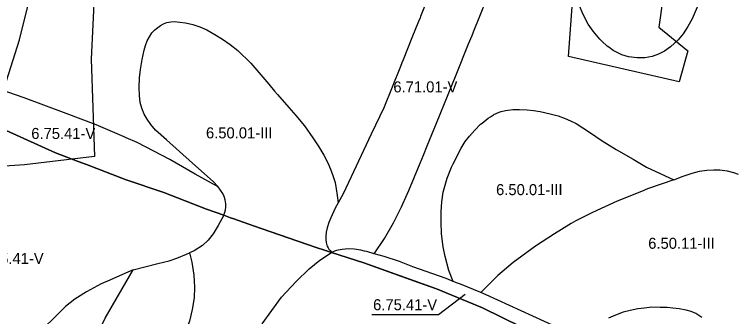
# Model space of a CAD drawing. Extents: x -555156 to -540209, y -1046851 to -1035695.
# Drawn here: x -543276 to -542621, y -1040830 to -1040556 of the extents above; entities that cross this region are included whole.
import ezdxf

# ---------------------------------------------------------------- set-up
doc = ezdxf.new("R2010")
doc.units = 0
for name, color, linetype in [('Vrstva 27', 7, 'Continuous'), ('Vrstva 28', 7, 'Continuous'), ('Vrstva 29', 7, 'Continuous')]:
    doc.layers.add(name, color=color, linetype=linetype)

msp = doc.modelspace()

# ---------------------------------------------------------------- linework, layer by layer
at = {"layer": 'Vrstva 27'}
msp.add_lwpolyline([(-542951.97, -1040828.05), (-542891.45, -1040828.05), (-542867.16, -1040809.73)], dxfattribs=at)
at = {"layer": 'Vrstva 28'}
for points in [[(-542875, -1040398.79), (-542873.7, -1040418.14), (-542873.31, -1040426.89), (-542872.91, -1040435.93), (-542872.91, -1040450.05), (-542873.7, -1040461.3), (-542875.53, -1040471.76), (-542876, -1040473.5), (-542878.66, -1040483.27), (-542881.47, -1040491.53), (-542883.11, -1040496.34), (-542907.05, -1040556.47), (-542907.61, -1040557.89), (-542908.19, -1040559.33), (-542909.52, -1040562.62), (-542915.49, -1040577.42), (-542923.48, -1040597.25), (-542924.63, -1040600.11), (-542925.9, -1040603.26), (-542941.01, -1040640.73), (-542952.35, -1040664.73), (-542973.03, -1040708.47), (-542977.75, -1040718.65), (-542982.34, -1040726.85)], [(-542719.25, -1040594.65), (-542725.26, -1040592.75), (-542733.18, -1040588.71), (-542737.18, -1040585.9), (-542738.71, -1040584.83), (-542743.47, -1040580.28), (-542745.28, -1040578.55), (-542749.82, -1040573.23), (-542751.4, -1040571.38), (-542756.03, -1040564.95), (-542760.37, -1040556.13), (-542763.8, -1040548.21), (-542766.94, -1040539.55), (-542769.03, -1040531.03), (-542770.82, -1040520.56), (-542775.87, -1040486.78), (-542776.18, -1040484.69)], [(-542647.85, -1040518.92), (-542650.77, -1040529.44), (-542650.84, -1040529.68), (-542653.68, -1040539.69), (-542657.11, -1040549.67), (-542661.75, -1040559.98), (-542665.63, -1040567.16), (-542669.96, -1040573.73), (-542674.29, -1040579.26), (-542681.46, -1040585.54), (-542686.69, -1040589.27), (-542692.07, -1040592.11), (-542698.04, -1040594.21), (-542704.46, -1040595.4), (-542711.63, -1040595.55), (-542719.25, -1040594.65)], [(-542940.22, -1040759.1), (-542932.3, -1040745.05), (-542924.98, -1040730.4), (-542919.71, -1040718.95), (-542918.37, -1040715.72), (-542908.09, -1040690.87), (-542905.17, -1040683.71), (-542901.7, -1040675.21), (-542893.31, -1040654.67), (-542882.73, -1040628.76), (-542881.46, -1040625.65), (-542875.38, -1040610.78), (-542864.2, -1040582.89), (-542861.09, -1040575.12), (-542859.74, -1040571.76), (-542841.99, -1040527.48)], [(-543091.12, -1040712.41), (-543095.47, -1040707.46), (-543114.31, -1040690.82), (-543137.83, -1040669.9), (-543147.84, -1040660.93), (-543152.02, -1040656), (-543155.46, -1040650.92), (-543158.14, -1040646.58), (-543160.24, -1040641.2), (-543161.58, -1040635.82), (-543162.33, -1040629.7), (-543162.63, -1040622.37), (-543162.36, -1040613.52), (-543161.47, -1040606.05), (-543159.97, -1040596.93), (-543158.18, -1040588.41), (-543156.94, -1040584.27), (-543155.32, -1040580), (-543153.27, -1040576.33), (-543150.97, -1040572.82), (-543148.24, -1040570.01), (-543146.8, -1040568.77), (-543145.76, -1040567.87), (-543143.29, -1040566.08), (-543140.56, -1040564.63), (-543137.57, -1040563.43), (-543133.98, -1040562.75), (-543130.57, -1040562.58), (-543125.62, -1040563), (-543120.58, -1040563.6), (-543113.84, -1040565.22), (-543107.52, -1040567.44), (-543101.38, -1040570.18), (-543094.12, -1040574.28), (-543087.04, -1040578.55), (-543080.21, -1040583.24), (-543073.13, -1040588.88), (-543061.35, -1040600.15), (-543045.22, -1040619.45), (-543039.87, -1040625.62), (-543037.16, -1040628.75), (-543027.02, -1040640.47), (-543020.59, -1040647.79), (-543012.97, -1040657.06), (-543005.36, -1040667.97), (-542999.83, -1040676.04), (-542995.2, -1040683.81), (-542991.76, -1040690.53), (-542989.25, -1040696.3), (-542987.11, -1040702.19), (-542985.15, -1040708.51), (-542984.04, -1040714.23), (-542983.1, -1040720.38), (-542982.34, -1040726.85)], [(-543091.12, -1040712.41), (-543111.91, -1040700.84), (-543134.91, -1040687.76), (-543164.45, -1040672.33), (-543174.27, -1040667.88), (-543176.28, -1040666.97), (-543193.18, -1040659.82), (-543201.63, -1040656.25), (-543228.82, -1040646.05), (-543266.64, -1040631.83), (-543288.6, -1040624.24), (-543307.42, -1040617.96), (-543322.58, -1040614.04), (-543328.36, -1040612.54), (-543337.74, -1040610.12), (-543337.84, -1040610.1), (-543342.85, -1040609.11), (-543353.68, -1040606.98), (-543361.64, -1040605.12), (-543376.95, -1040601.54), (-543406.05, -1040594.73)], [(-543085.78, -1040738.2), (-543101.67, -1040732.49), (-543140.14, -1040717.52), (-543174.28, -1040705.94), (-543210.23, -1040692.22), (-543217.71, -1040689.38), (-543238.43, -1040681.52), (-543299.21, -1040654.19), (-543333.45, -1040639.76), (-543338.53, -1040637.62), (-543366.74, -1040625.24), (-543373.17, -1040622.42), (-543394.76, -1040609.36), (-543404.86, -1040603.25), (-543412.12, -1040599.04)], [(-543404.86, -1040603.25), (-543394.76, -1040609.36), (-543373.17, -1040622.42), (-543366.74, -1040625.24), (-543338.53, -1040637.62), (-543333.45, -1040639.76), (-543299.21, -1040654.19), (-543238.43, -1040681.52), (-543217.71, -1040689.38), (-543210.23, -1040692.22), (-543174.28, -1040705.94), (-543140.14, -1040717.52), (-543101.67, -1040732.49), (-543085.78, -1040738.2)], [(-542878.08, -1040798.15), (-542882.13, -1040788.09), (-542885.52, -1040775.54), (-542887.35, -1040766.64), (-542888.66, -1040754.87), (-542888.92, -1040744.15), (-542888.92, -1040735), (-542888.4, -1040726.1), (-542887.09, -1040717.21), (-542883.69, -1040704.4), (-542879.54, -1040694.69), (-542878.21, -1040691.58), (-542870.87, -1040677.46), (-542867.2, -1040671.39), (-542863.44, -1040666.52), (-542858.49, -1040660.97), (-542853.28, -1040655.68), (-542851.98, -1040654.63), (-542846.54, -1040650.21), (-542844.41, -1040648.83), (-542841.67, -1040647.05), (-542841.4, -1040646.93), (-542836.47, -1040644.66), (-542834.66, -1040644.17), (-542830.75, -1040643.12), (-542824.09, -1040642.36), (-542817.95, -1040642.27), (-542811.29, -1040642.53), (-542805.4, -1040643.21), (-542799.34, -1040643.98), (-542790.46, -1040646.11), (-542783.12, -1040648.16), (-542776.64, -1040650.47), (-542771.77, -1040652.6), (-542766.87, -1040655.03), (-542754.77, -1040662.95), (-542743.12, -1040670.72), (-542730.57, -1040678.65), (-542715.19, -1040687.46), (-542703.09, -1040694.49), (-542678.39, -1040706.13)], [(-542678.39, -1040706.13), (-542669.87, -1040702.69), (-542661.81, -1040700.15), (-542654.93, -1040698.2), (-542648.34, -1040697.18), (-542642.19, -1040696.84), (-542636.56, -1040697.01), (-542630.07, -1040698.03), (-542624.18, -1040699.4), (-542619.91, -1040700.94)], [(-542678.39, -1040706.13), (-542701.16, -1040714.05), (-542703.66, -1040714.92), (-542706, -1040715.87), (-542729.54, -1040725.39), (-542752.02, -1040735.59), (-542767.09, -1040743.33), (-542771.36, -1040745.52), (-542786.52, -1040754.94), (-542803.51, -1040766.19), (-542823.9, -1040781.09), (-542837.75, -1040792.86)], [(-543085.01, -1040735.3), (-543084.46, -1040733.25), (-543084.12, -1040730.77), (-543084.12, -1040727.87), (-543084.54, -1040724.2), (-543085.57, -1040721.21), (-543086.85, -1040718.47), (-543088.81, -1040715.49), (-543091.12, -1040712.41)], [(-542982.34, -1040726.85), (-542985.01, -1040731.63), (-542988.94, -1040740.51), (-542990.81, -1040744.61), (-542992.26, -1040749.65), (-542993.29, -1040753.58), (-542993.51, -1040757.47), (-542993.51, -1040760.4), (-542993.26, -1040762.6), (-542992.78, -1040764.45), (-542992.57, -1040765.08), (-542992.19, -1040766.26), (-542991.41, -1040767.67), (-542991.32, -1040767.83), (-542990.73, -1040768.89), (-542989.7, -1040770.16)], [(-543085.78, -1040738.2), (-543090.89, -1040747.49), (-543095.61, -1040754.88), (-543099.97, -1040760.7), (-543105.3, -1040765.54), (-543112.69, -1040770.39), (-543117.02, -1040772.37)], [(-543085.78, -1040738.2), (-543085.01, -1040735.3)], [(-543085.78, -1040738.2), (-543079.73, -1040740.37), (-543076.8, -1040741.42), (-543059.07, -1040747.79), (-543036.45, -1040755.62), (-543002.41, -1040767.4), (-542994.61, -1040769.9), (-542988.31, -1040771.92)], [(-542988.31, -1040771.92), (-542994.61, -1040769.9), (-543002.41, -1040767.4), (-543059.07, -1040747.79), (-543076.8, -1040741.42), (-543079.73, -1040740.37), (-543085.78, -1040738.2)], [(-542949.59, -1040773.02), (-542940.22, -1040759.1)], [(-543168.15, -1040787.72), (-543145.63, -1040782.02), (-543135.33, -1040779.36), (-543128.43, -1040776.93), (-543119.59, -1040773.54), (-543117.02, -1040772.37)], [(-543117.02, -1040772.37), (-543114.91, -1040780.64)], [(-543051.23, -1040836.43), (-543033.64, -1040812.47), (-543020.29, -1040798.26), (-543008.63, -1040786.6), (-542998.88, -1040778.96), (-542988.31, -1040771.92)], [(-542989.7, -1040770.16), (-542988.31, -1040771.92)], [(-542949.59, -1040773.02), (-542956.25, -1040771.14), (-542958.47, -1040770.67), (-542961.88, -1040769.94), (-542967.77, -1040769), (-542973.4, -1040768.66), (-542978.7, -1040769.09), (-542982.28, -1040769.69), (-542983.7, -1040770.12), (-542985.75, -1040770.74), (-542988.31, -1040771.92)], [(-542988.31, -1040771.92), (-542959.22, -1040781.23)], [(-542750.36, -1040868.71), (-542763.73, -1040862.75), (-542777.64, -1040856.56), (-542816.73, -1040839.15), (-542851.59, -1040821.98), (-542893.18, -1040804.96), (-542959.22, -1040781.23), (-542988.31, -1040771.92)], [(-542878.08, -1040798.15), (-542884.59, -1040795.54), (-542914.85, -1040784.97), (-542926.89, -1040780.19), (-542940.71, -1040775.67), (-542949.59, -1040773.02)], [(-543114.91, -1040780.64), (-543113, -1040792.52), (-543112.57, -1040803.33), (-543112.79, -1040813.08), (-543114.48, -1040823.69), (-543117.02, -1040834.08), (-543121.05, -1040844.04), (-543127.62, -1040856.34), (-543132.71, -1040864.4), (-543140.55, -1040877.5), (-543166.14, -1040918.69), (-543197.89, -1040967.9), (-543214.21, -1040997.22), (-543233.03, -1041028.81), (-543244.9, -1041062.1), (-543267.79, -1041121.9), (-543281.99, -1041158.59)], [(-542959.22, -1040781.23), (-542909.59, -1040799.06), (-542893.18, -1040804.96), (-542851.59, -1040821.98), (-542816.73, -1040839.15), (-542777.68, -1040856.54)], [(-543293.87, -1041005.52), (-543253.63, -1040944.47), (-543217.93, -1040882.13), (-543193.27, -1040831.47), (-543168.15, -1040787.72)], [(-543168.15, -1040787.72), (-543177.6, -1040791.96), (-543189.11, -1040796.93), (-543197, -1040800.47), (-543210.35, -1040807.47), (-543220.95, -1040814.25), (-543229.21, -1040820.83), (-543239.6, -1040831.01), (-543248.92, -1040840.12), (-543257.19, -1040850.09), (-543268, -1040863.45), (-543278.38, -1040878.72)], [(-542837.75, -1040792.86), (-542852.98, -1040808.28)], [(-542852.98, -1040808.28), (-542871.52, -1040800.77), (-542874.38, -1040799.63), (-542878.08, -1040798.15)], [(-542756.44, -1040853.01), (-542785, -1040839.22), (-542848.26, -1040810.19), (-542852.98, -1040808.28)], [(-542653.08, -1040830.93), (-542655.56, -1040828.88), (-542658.46, -1040827.17), (-542662.58, -1040825.42), (-542667.1, -1040824.05), (-542673.33, -1040823.03), (-542679.22, -1040822.35), (-542684.34, -1040821.83), (-542690.75, -1040821.66), (-542698.09, -1040821.58), (-542704.83, -1040822.35), (-542710.8, -1040823.11), (-542717.89, -1040824.48), (-542724.12, -1040826.1), (-542731.25, -1040828.69), (-542737.56, -1040831.59)]]:
    msp.add_lwpolyline(points, dxfattribs=at)
at = {"layer": 'Vrstva 29'}
for points in [[(-542766.566372, -1040495.592429), (-542784.29, -1040494.4), (-542802.33, -1040486.92), (-542791.03, -1040459.74), (-542784.88, -1040456.21), (-542764.89, -1040456.42), (-542759.14, -1040448.05), (-542753.13, -1040433.57), (-542745.45, -1040429.18), (-542715.09, -1040432.92), (-542681.35, -1040438.44), (-542666.68, -1040444.44), (-542674.11, -1040472.37), (-542679.46, -1040502.63), (-542684.004827, -1040502.241349), (-542684.386999, -1040513.962001), (-542691.771001, -1040567.565992), (-542665.729, -1040589.049996), (-542673.390999, -1040617.079993), (-542773.690999, -1040594.150007), (-542766.566372, -1040495.592429)], [(-543203.043003, -1040533.644997), (-543205.959003, -1040596.590006), (-543203.105995, -1040684.815999), (-543266.397004, -1040692.522995), (-543339.110996, -1040697.288998), (-543290.863999, -1040640.979001), (-543270.945994, -1040579.150993), (-543247.329994, -1040483.771991)]]:
    msp.add_lwpolyline(points, dxfattribs=at)

# ---------------------------------------------------------------- texts
at = {"layer": 'Vrstva 27'}
for s, p in [('6.71.01-V', (-542932.331006, -1040626.77)), ('6.75.41-V', (-543260.291006, -1040669.01)), ('6.50.01-III', (-543102.056548, -1040668.47)), ('6.50.01-III', (-542839.316548, -1040719.94)), ('6.50.11-III', (-542701.506548, -1040768.56)), ('6.75.41-V', (-543307.051006, -1040782.31)), ('6.75.41-V', (-542950.690576, -1040824.26))]:
    msp.add_text(s, height=10, dxfattribs=at).set_placement(p)

doc.saveas('drawing.dxf')
